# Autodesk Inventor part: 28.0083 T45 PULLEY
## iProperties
Created: 2006-12
Document SubType Name: Modeling
Designer: Andy Moles
Material: Aluminum-6061
Part Number: 28.0083 T45 PULLEY
Density: 2.71 g/cm^3
Author: Andy Moles
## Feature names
1. Extrusion1
2. Extrusion3
3. Extrusion4
4. Mirror1
5. Extrusion5
